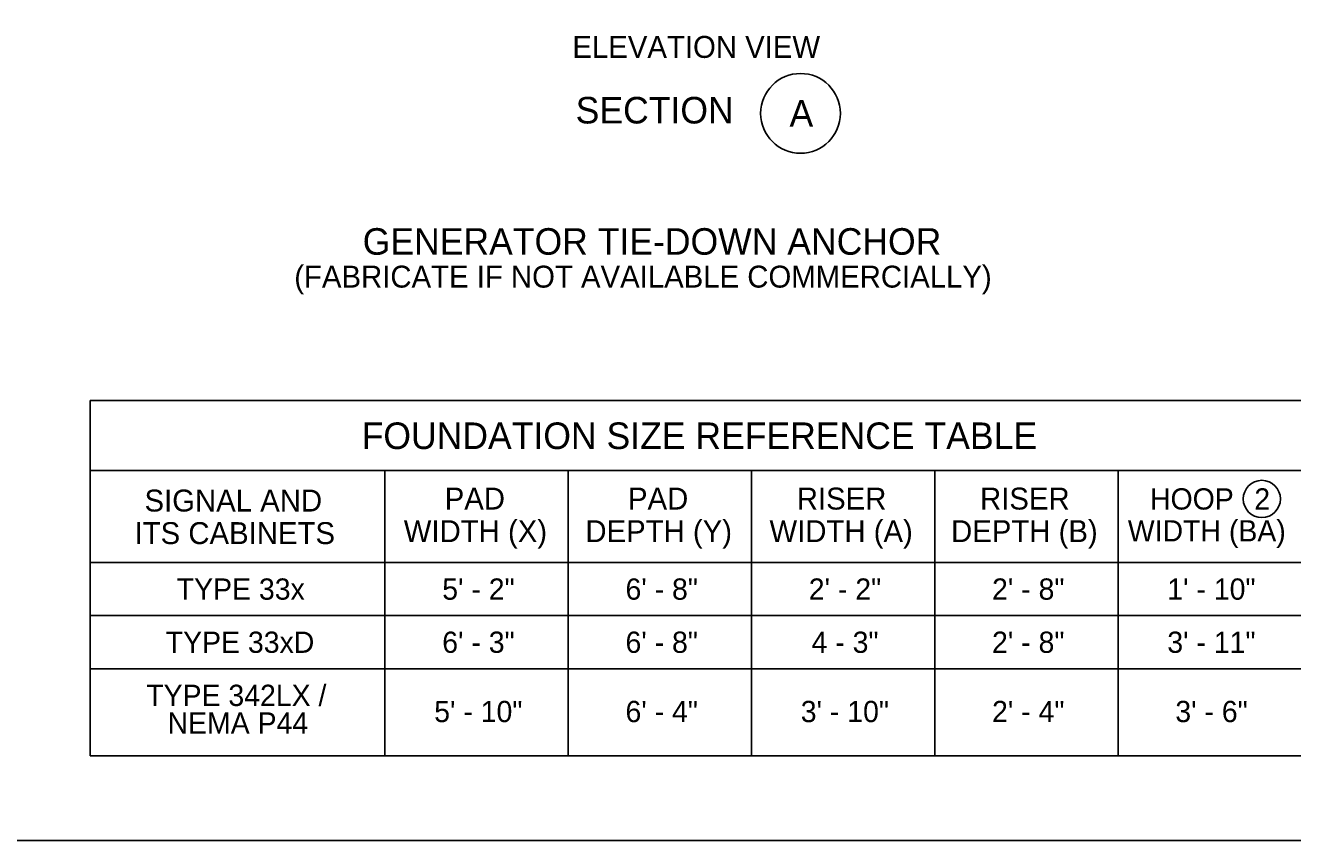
# Model space of a CAD drawing. Extents: x 99862 to 103151, y 100000 to 117076.
# Drawn here: x 101432 to 102386, y 109000 to 109613 of the extents above; entities that cross this region are included whole.
import ezdxf

# ---------------------------------------------------------------- set-up
doc = ezdxf.new("R2010")
doc.units = 0
for name, color, linetype in [('Level 1', 7, 'Continuous'), ('Level 20', 7, 'Continuous'), ('Level 40', 7, 'Continuous')]:
    doc.layers.add(name, color=color, linetype=linetype)

msp = doc.modelspace()

# ---------------------------------------------------------------- linework, layer by layer
at = {"layer": 'Level 1'}
msp.add_lwpolyline([(99862, 108999.5), (103151, 108999.5), (103151, 111075.5), (99862, 111075.5)], close=True, dxfattribs=at)
at = {"layer": 'Level 20'}
for centre, radius in [((102015.26, 109546.89), 30), ((102362.31, 109256.7), 14)]:
    msp.add_circle(centre, radius, dxfattribs=at)
at = {"layer": 'Level 40'}
for p, q in [((101702.57, 109278.01), (101702.57, 109063.47)), ((101840.46, 109278.01), (101840.46, 109063.47)), ((101978.34, 109278.01), (101978.34, 109063.47)), ((102116.23, 109278.01), (102116.23, 109063.47)), ((102254.12, 109278.01), (102254.12, 109063.47)), ((101480.89, 109208.85), (102529.89, 109208.85)), ((101480.89, 109168.85), (102529.89, 109168.85)), ((101480.89, 109128.85), (102529.89, 109128.85))]:
    msp.add_line(p, q, dxfattribs=at)
for points in [[(101480.89, 109330.69), (102529.89, 109330.69), (102529.89, 109278.01), (101480.89, 109278.01)], [(101480.89, 109278.01), (102529.89, 109278.01), (102529.89, 109063.47), (101480.89, 109063.47)]]:
    msp.add_lwpolyline(points, close=True, dxfattribs=at)

# ---------------------------------------------------------------- texts
at = {"layer": 'Level 20'}
for s, height, p in [('ELEVATION VIEW', 16.5, (101843.62, 109588.64)), ('SECTION', 20, (101846.07, 109539.27)), ('A', 20, (102006.96, 109536.89)), ('GENERATOR TIE-DOWN ANCHOR', 20, (101685.84, 109440.48)), ('(FABRICATE IF NOT AVAILABLE COMMERCIALLY)', 16.5, (101634.35, 109415.76)), ('FOUNDATION SIZE REFERENCE TABLE', 20, (101685.04, 109294.25)), ('SIGNAL AND', 16.5, (101521.68, 109247.21)), ('PAD', 16.5, (101747.54, 109248.7)), ('PAD', 16.5, (101885.43, 109248.7)), ('RISER', 16.5, (102012.42, 109248.7)), ('RISER', 16.5, (102150.3, 109248.7)), ('HOOP ', 16, (102278.19, 109248.7)), ('2', 16, (102356.69, 109248.7)), ('WIDTH (X)', 16.5, (101716.74, 109224.2)), ('DEPTH (Y)', 16.5, (101853.37, 109224.2)), ('WIDTH (A)', 16.5, (101991.89, 109224.2)), ('DEPTH (B)', 16.5, (102128.52, 109224.2)), ('WIDTH (BA)', 16, (102261.5, 109224.7)), ('ITS CABINETS', 16.5, (101514.21, 109222.71)), ('TYPE 33x', 16, (101545.94, 109180.85)), ('5\' - 2"', 16, (101745.69, 109180.85)), ('6\' - 8"', 16, (101883.57, 109180.85)), ('2\' - 2"', 16, (102021.46, 109180.85)), ('2\' - 8"', 16, (102159.35, 109180.85)), ('1\' - 10"', 16, (102291.19, 109180.85)), ('TYPE 33xD', 16, (101537.67, 109140.85)), ('6\' - 3"', 16, (101745.69, 109140.85)), ('6\' - 8"', 16, (101883.57, 109140.85)), ('4 - 3"', 16, (102023.53, 109140.85)), ('2\' - 8"', 16, (102159.35, 109140.85)), ('3\' - 11"', 16, (102291.19, 109140.85)), ('TYPE 342LX /', 16, (101522.97, 109100.86)), ('5\' - 10"', 16, (101739.64, 109088.71)), ('6\' - 4"', 16, (101883.57, 109088.71)), ('3\' - 10"', 16, (102015.42, 109088.71)), ('2\' - 4"', 16, (102159.35, 109088.71)), ('3\' - 6"', 16, (102297.23, 109088.71)), ('NEMA P44', 16, (101539.01, 109080.03))]:
    msp.add_text(s, height=height, dxfattribs=at).set_placement(p)

doc.saveas('drawing.dxf')
